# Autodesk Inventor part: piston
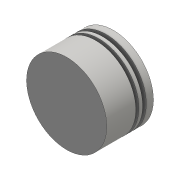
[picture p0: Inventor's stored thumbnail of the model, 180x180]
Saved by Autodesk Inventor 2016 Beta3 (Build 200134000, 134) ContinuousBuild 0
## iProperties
Created: 2016-03
Part Number: piston
Material: Generic
Document SubType Name: Modeling
Designer: Gaurav
Density: 1 g/cm^3
Appearance: Default
Author: Gaurav
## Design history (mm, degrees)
sketch "Sketch1"
  geometry: L1 (0, 0)-(0, -12.5); L2 (0, -12.5)-(9.043, -12.5); L3 (9.043, -12.5)-(9.043, -11.082); L4 (9.043, -11.082)-(10.018, -11.082); L5 (10.018, -11.082)-(10.018, -12.5); L6 (10.018, -12.5)-(11.17, -12.5); L7 (11.17, -12.5)-(11.17, -11.082); L8 (11.17, -11.082)-(12.323, -11.082); L9 (12.323, -11.082)-(12.323, -12.5); L10 (12.323, -12.5)-(14.539, -12.5); L11 (14.539, -12.5)-(14.539, 0); L12 (14.539, 0)-(0, 0)
  constraints: 24 end point, 8 perpendicular, 6 point on line, 1 vertical
  dimensions: "d0" = 12.5 distance of L10.end L11.end
revolve "Revolution1" sketch "Sketch1" stored, may be unused: angle "d1" = 90 deg
body "Solid1"
